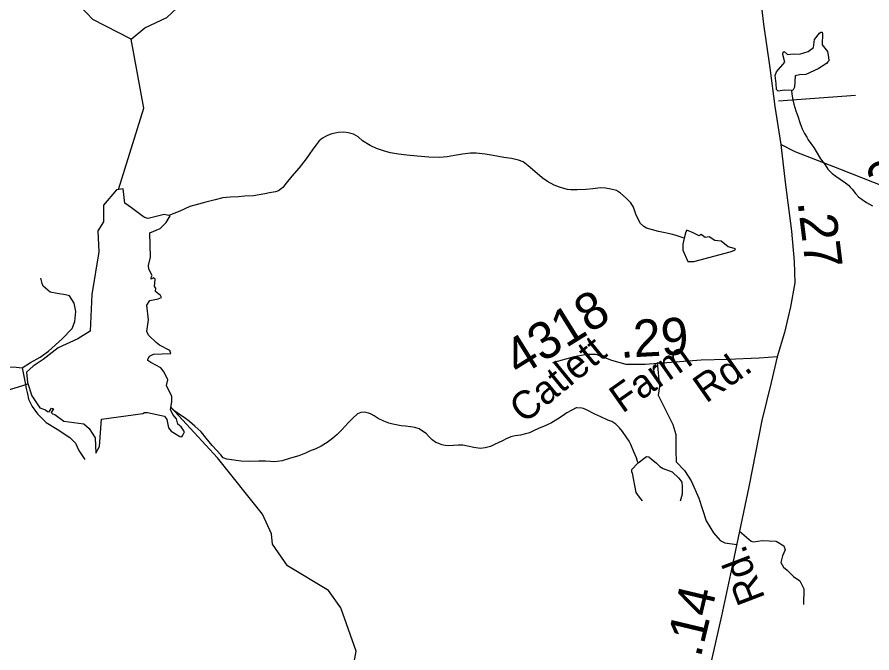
# Model space of a CAD drawing. Extents: x 2001466 to 31450019, y -30647475 to 847247.
# Drawn here: x 2159166 to 2164923, y 778978 to 783261 of the extents above; entities that cross this region are included whole.
import ezdxf

# ---------------------------------------------------------------- set-up
doc = ezdxf.new("R2010")
doc.units = 0
for name, color, linetype in [('Exist Hydrographic Creek Single Shore', 7, 'Continuous'), ('Exist Hydrographic Misc Water Feature', 7, 'Continuous'), ('Exist Hydrographic Pond Under 1500 Sq Ft', 7, 'Continuous'), ('Exist Road Non-System Type 51', 7, 'Continuous'), ('Exist Road Secondary Mileage Hundredths English Label', 7, 'Continuous'), ('Exist Road Secondary Type 51 Attributed', 7, 'Continuous'), ('Exist Road Secondary Type 51 Label', 7, 'Continuous'), ('Exist Road Secondary Type 51 Number Label', 7, 'Continuous')]:
    doc.layers.add(name, color=color, linetype=linetype)

msp = doc.modelspace()

# ---------------------------------------------------------------- linework, layer by layer
at = {"layer": 'Exist Hydrographic Creek Single Shore'}
for points in [[(2159934.2, 783111.8), (2159675.2, 783245.1), (2159591.3, 783335.4), (2159564.3, 783677.1), (2159497.2, 783826.2), (2159545.2, 784195.9), (2159543.3, 784428.8), (2159483.3, 784702.3), (2159457.2, 784952.2), (2159562.2, 785570.1), (2159692.2, 786062.8), (2159666.2, 786201.1), (2159591.3, 786284.7), (2159548.3, 786518.4), (2159498.2, 786627.7), (2159347.3, 786758.8), (2159419.3, 787226.4), (2159543.3, 787335.5), (2159609.2, 787462), (2159684.2, 787519.5), (2159784.3, 787537.1)], [(2159849.3, 782099.5), (2160020.3, 782647.6), (2159934.2, 783111.8)], [(2157629.3, 780016.8), (2157644.3, 780009.6), (2157785.2, 780052.6), (2157860.3, 780119.9), (2158251.3, 780203.7), (2158798.2, 780625.5), (2158914.2, 780692), (2159203.8, 780779.7)], [(2159203.8, 780779.7), (2159239.1, 780790.4)], [(2162195.3, 776678.1), (2161700.3, 777183.6), (2161565.1, 777498.1), (2161429.2, 777940.4), (2161419.2, 778298.2), (2161385.3, 778364.5), (2161376.3, 778581.3), (2161449.3, 778989.8), (2161347.2, 779280.6), (2161263.3, 779397.2), (2160987.3, 779563.5), (2160886.2, 779710), (2160878.2, 779779), (2160818.1, 779911.5), (2160516.3, 780291.7), (2160201, 780633.1)]]:
    msp.add_lwpolyline(points, dxfattribs=at)
at = {"layer": 'Exist Hydrographic Misc Water Feature'}
for points in [[(2159934.2, 783111.8), (2160025.2, 783188.7), (2160175.3, 783257.8), (2160240.9, 783320.9)], [(2164380.8, 782765.9), (2164384.2, 782742.2), (2164390.8, 782702.3), (2164396.7, 782674.2), (2164411.1, 782628.2), (2164423.8, 782594.2), (2164439.8, 782544.4), (2164453.7, 782508.6), (2164470.1, 782476.5), (2164484.5, 782450.8), (2164494.3, 782433.1), (2164512.8, 782408.8), (2164532.7, 782383), (2164548.9, 782355.1), (2164577.2, 782305.3), (2164607.5, 782265.4), (2164627.2, 782235.7), (2164655.7, 782207.8), (2164679.5, 782190), (2164709.6, 782170), (2164745.7, 782144.3), (2164766, 782128.3), (2164777.9, 782114.7), (2164790, 782100.7), (2164811.9, 782072.6), (2164832.2, 782050.9), (2164858.7, 782031.1), (2164886.4, 782011.1), (2164927, 781989.5)], [(2163658.6, 781771.1), (2163638.2, 781778.3), (2163604.4, 781789.9), (2163570.4, 781799.6), (2163530, 781807.7), (2163486.1, 781817.1), (2163446.1, 781826.9), (2163406.1, 781839), (2163388.1, 781850.7), (2163365.7, 781870.7), (2163352, 781894.7), (2163333.5, 781932.3), (2163317.3, 781980.2), (2163298.9, 782010.2), (2163268.5, 782041.9), (2163230.8, 782075.7), (2163202.5, 782091.7), (2163164.6, 782101.5), (2163128.7, 782107.3), (2163094.2, 782110.9), (2163042.8, 782104.5), (2162996.6, 782100.5), (2162938.8, 782097.9), (2162894.5, 782097.7), (2162872.8, 782099.8), (2162848.6, 782105.5), (2162818.4, 782115.3), (2162782.5, 782129.2), (2162738.5, 782153), (2162702.4, 782178.7), (2162654, 782220.5), (2162608, 782258.3), (2162574, 782285.7), (2162542, 782297.9), (2162495.5, 782307.3), (2162443.4, 782315.2), (2162371.6, 782328.9), (2162317.7, 782336.6), (2162257.4, 782344.2), (2162219.5, 782343.8), (2162165.7, 782337.7), (2162111.2, 782327.3), (2162061.8, 782319), (2162014, 782314.9), (2161940, 782316.3), (2161860, 782323.9), (2161791.5, 782331.5), (2161735.5, 782337.1), (2161681.4, 782346.9), (2161641.4, 782356.6), (2161587.5, 782376.5), (2161543.6, 782396.1), (2161493.2, 782427.7), (2161463, 782453.7), (2161431, 782471.6), (2161395, 782481.1), (2161367.1, 782484.9), (2161327.3, 782482.8), (2161307, 782478.6), (2161286.7, 782474.8), (2161272.9, 782470.8), (2161247.1, 782458.4), (2161223.5, 782444.1), (2161201.2, 782428.1), (2161179.7, 782400.1), (2161157.5, 782370.1), (2161133.5, 782335.6), (2161112, 782305.6), (2161066.3, 782245.6), (2161016.8, 782189), (2160977.1, 782143.1), (2160955.3, 782112.7), (2160945.3, 782102.8), (2160927, 782090.6), (2160907.3, 782082.6), (2160865.5, 782076.3), (2160833.5, 782070.2), (2160757.4, 782057.8), (2160699.2, 782055.3), (2160657.4, 782051.1), (2160599.8, 782046.8), (2160551.8, 782042.7), (2160499.7, 782030.3), (2160438, 782014.1), (2160387.7, 782001.7), (2160329.9, 781985.4), (2160262.5, 781953), (2160187.5, 781923.7)], [(2160009.1, 781921.1), (2159936.6, 781975.4), (2159891.3, 782006.7), (2159880.8, 782104.4), (2159835.5, 782097.4), (2159748.4, 781992.8), (2159748.4, 781881.2), (2159710, 781821.9), (2159717, 781679), (2159668.2, 781393), (2159657.8, 781145.4), (2159574.1, 781093.1), (2159441.7, 781033.8), (2159340.7, 780953.6), (2159274.4, 780908.3), (2159229.1, 780870), (2159236.1, 780800.2), (2159264, 780709.5), (2159319.7, 780629.3), (2159356.7, 780614.8), (2159371.3, 780604.7), (2159381.3, 780601.1), (2159398.6, 780627.5), (2159412.1, 780621.8), (2159395.9, 780597.4), (2159404.3, 780589.2), (2159420.8, 780584), (2159480, 780538.7), (2159616, 780521.2), (2159650.8, 780489.9), (2159692.6, 780427.1), (2159696.1, 780322.5), (2159720.5, 780367.8), (2159734.4, 780552.6), (2160012.4, 780590.2)], [(2160012.4, 780590.2), (2160024.9, 780596.8), (2160044.8, 780597.7), (2160158.7, 780573.6), (2160174.5, 780550.3), (2160185.3, 780493.7), (2160203.6, 780470.4), (2160225.2, 780457.1), (2160261, 780436.3), (2160275.1, 780433.8), (2160281.7, 780444.6), (2160293.4, 780467.1), (2160271.8, 780500.4), (2160247.6, 780518.7), (2160238.5, 780555.3), (2160214.4, 780583.5), (2160198.6, 780618.5), (2160206.9, 780668.4), (2160208.6, 780704.1), (2160172, 780779.8), (2160181.1, 780817.6), (2160156.2, 780869.2), (2160132.9, 780898.3), (2160066.4, 780934.9), (2160047.3, 780947.4), (2160045.7, 780956.2), (2160057.3, 780975.6), (2160085.6, 780989.8), (2160200.3, 780995.6), (2160194.4, 781013.9), (2160125.5, 781050.5), (2160103, 781068.6), (2160049.8, 781118.5), (2160039, 781142.5), (2160049.8, 781221.7), (2160039.8, 781319.2), (2160059.8, 781352.5), (2160116.3, 781362.4), (2160138.8, 781371.6), (2160132.1, 781385.7), (2160098.9, 781412.3), (2160101.3, 781434), (2160092.2, 781445.3), (2160094.7, 781496.3), (2160083.9, 781503.8), (2160069.8, 781494.7), (2160068.1, 781506.3), (2160076.4, 781519.6), (2160054, 781562.9), (2160051.5, 781587.8), (2160063.9, 781642.7), (2160059, 781807.9), (2160130.4, 781837.4), (2160170.3, 781876.5), (2160197.8, 781921.4), (2160155.4, 781931), (2160049, 781904.4), (2160023.2, 781911.4), (2160009.1, 781921.1)], [(2163658.6, 781771.1), (2163650.4, 781730.8), (2163649.1, 781691), (2163683.4, 781613.4), (2163724.6, 781615.4), (2163969.6, 781680), (2163999.8, 781690.3), (2164005.3, 781700.6), (2163954.5, 781712.3), (2163908.5, 781750.7), (2163885.9, 781752.8), (2163864.6, 781755.5), (2163827.5, 781781), (2163800.1, 781776.2), (2163774, 781795.4), (2163760.3, 781787.8), (2163719.8, 781806.4), (2163677.2, 781824.9), (2163669.7, 781815.3), (2163658.6, 781771.1)], [(2160553.4, 780291.1), (2160537.6, 780313), (2160511.2, 780340.9), (2160479.4, 780374.6), (2160438.8, 780424.5), (2160405, 780466.1), (2160362.7, 780505.8), (2160326.4, 780537.6), (2160292, 780563.5), (2160260, 780583.4), (2160227.8, 780607.3), (2160200.6, 780630.2)], [(2162931.2, 780628.5), (2162902.9, 780612.1), (2162869.3, 780594), (2162837.3, 780572.1), (2162805.3, 780551.8), (2162765.5, 780527.4), (2162727.8, 780509.1), (2162677.8, 780489.1), (2162643.9, 780472.7), (2162616, 780460.7), (2162590, 780452.5), (2162556, 780444.3), (2162520.3, 780440.3), (2162492.2, 780434), (2162460, 780419.8), (2162434.8, 780405.8), (2162410.6, 780395.7), (2162380.6, 780381.5), (2162354.2, 780369.3), (2162318.7, 780359.2), (2162284.7, 780355), (2162242.8, 780360.6), (2162199, 780370.5), (2162168.4, 780376.3), (2162138.5, 780377.9), (2162104.6, 780375.8), (2162070.8, 780373.6), (2162048.5, 780375.4), (2162026.7, 780379.5), (2162006.2, 780387.4), (2161986.3, 780395.3), (2161962.5, 780413.1), (2161942, 780432.8), (2161920.1, 780454.8), (2161896.5, 780470.6), (2161874, 780486.5), (2161844.2, 780496.3), (2161815.9, 780500.2), (2161781.9, 780504.2), (2161751.7, 780507.8), (2161720, 780513.5), (2161696, 780519.5), (2161669.7, 780525.5), (2161635.5, 780539.2), (2161597.5, 780556.7), (2161569.7, 780574.7), (2161549.6, 780586.7), (2161535.6, 780592.5), (2161503.2, 780600.2), (2161481.3, 780598.3), (2161457.5, 780588.1), (2161427.8, 780560.1), (2161400.1, 780531.8), (2161376.3, 780505.8), (2161350.3, 780477.3), (2161320.5, 780449.3), (2161290.6, 780423.1), (2161254.5, 780395.2), (2161214.7, 780370.8), (2161177, 780352.6), (2161135.2, 780336.2), (2161109.3, 780324.3), (2161063.2, 780305.7), (2161007.6, 780289.8), (2160951.4, 780271.5), (2160917.4, 780266.9), (2160889.9, 780265), (2160871.5, 780267), (2160839.5, 780268.5), (2160793.5, 780268.6), (2160732, 780268.2), (2160675.6, 780269.8), (2160642, 780273.7), (2160609.8, 780277.3), (2160579.3, 780283.2), (2160553.4, 780291.1)], [(2163349.7, 780259), (2163344.8, 780267), (2163337, 780290.8), (2163320.6, 780332.7), (2163300.5, 780380.8), (2163287.8, 780404.5), (2163267.7, 780434.4), (2163243.7, 780468.4), (2163223.8, 780494.2), (2163197.6, 780518), (2163171.5, 780535.7), (2163145.3, 780545.8), (2163097.3, 780567.3), (2163057.3, 780587.1), (2163005, 780612.8), (2162981, 780624.6), (2162969.1, 780626.8), (2162934.8, 780628.3), (2162931.2, 780628.5)], [(2163349.7, 780259), (2163404.1, 780299.9), (2163421.5, 780298.2), (2163437.3, 780284.1), (2163473.1, 780256.6), (2163494.7, 780234.2), (2163517.1, 780220), (2163577, 780197.6), (2163623.5, 780154.3), (2163643.5, 780126.9), (2163645.1, 780096.9), (2163644.3, 780047), (2163632.7, 779999.6)], [(2163349.7, 780259), (2163304.3, 780211.7), (2163303.5, 780200.9), (2163309.3, 780189.3), (2163332.6, 780058.7), (2163356.7, 780027.9), (2163376.6, 780001.3)]]:
    msp.add_lwpolyline(points, dxfattribs=at)
at = {"layer": 'Exist Hydrographic Pond Under 1500 Sq Ft'}
msp.add_lwpolyline([(2164395.1, 783014), (2164436.5, 783010.9), (2164494.9, 783027.9), (2164529.6, 783055.3), (2164537.3, 783110.6), (2164571.2, 783153.1), (2164578.6, 783158.4), (2164587.1, 783159.4), (2164591.4, 783150.9), (2164589.3, 783073.4), (2164624.5, 783029.1), (2164630.2, 782990.4), (2164632.1, 782967.2), (2164625.6, 782959.2), (2164617.9, 782948.8), (2164561.7, 782913.3), (2164477.9, 782875.1), (2164435.3, 782872.9), (2164407, 782864.8), (2164402.6, 782788), (2164389.9, 782766.8), (2164335.5, 782768.1), (2164292.3, 782762.6), (2164281.7, 782773.2), (2164278.5, 782812.4), (2164272.2, 782866.6), (2164280.5, 782891.7), (2164336.8, 782957.8), (2164323.1, 783007.7), (2164325.2, 783024.7), (2164331.5, 783030), (2164353.8, 783009.8), (2164395.1, 783014)], dxfattribs=at)
at = {"layer": 'Exist Road Non-System Type 51'}
msp.add_line((2164812.5, 782732.9), (2164293.7, 782693.5), dxfattribs=at)
for points in [[(2159200, 780898.7), (2159257.1, 780934), (2159320.9, 780970.9), (2159376.3, 781009.6), (2159468.6, 781093.6), (2159535.7, 781162.4), (2159554.2, 781211.1), (2159560.9, 781276.6), (2159550.8, 781333.7), (2159518.9, 781384.1), (2159492.1, 781390.9), (2159435, 781399.3), (2159388, 781407.7), (2159342.1, 781448.6), (2159334.3, 781466.4), (2159325.9, 781501.7)], [(2163476, 780933.6), (2163492.1, 780773.2), (2163484.1, 780714.4), (2163582.9, 780516.6), (2163601.6, 780449.8), (2163601.6, 780340.2), (2163604.3, 780265.4), (2163660.4, 780206.6), (2163705.8, 780137.1), (2163756.6, 780019.5), (2163807.3, 779867.1), (2163855.4, 779786.9), (2163900.8, 779736.1), (2163932.9, 779720.1), (2164012.9, 779707.3)], [(2157623, 780359.6), (2157789.5, 780356.2), (2157997.6, 780430.1), (2158131.9, 780463.7), (2158224.2, 780534.2), (2158276.2, 780584.6), (2158342.3, 780626.6), (2158555.5, 780700.5), (2158755.2, 780804.7), (2158866, 780850), (2158983.5, 780890.3), (2159054, 780905.4), (2159159.8, 780902.1), (2159200, 780898.7)], [(2159200, 780898.7), (2159220.2, 780796.3), (2159226.9, 780759.3)], [(2159226.9, 780759.3), (2159235.3, 780722.4), (2159243, 780687), (2159267.2, 780636.7), (2159302.4, 780588), (2159361.2, 780530.9), (2159435, 780485.5), (2159520.6, 780428.4), (2159559.2, 780389.8), (2159582.7, 780341.1), (2159621.3, 780280.6)], [(2164030.4, 779797.6), (2164109.5, 779730.6), (2164125.4, 779726.2), (2164184, 779736.1), (2164277.5, 779730.8), (2164330.9, 779698.7), (2164338.9, 779672), (2164320.2, 779631.9), (2164309.6, 779586.4), (2164328.3, 779554.4), (2164352.3, 779535.7), (2164395, 779492.9), (2164437.8, 779463.5), (2164464.5, 779410), (2164461.8, 779303.1)]]:
    msp.add_lwpolyline(points, dxfattribs=at)
at = {"layer": 'Exist Road Secondary Type 51 Attributed'}
for points in [[(2163686.4, 786619.3), (2163781.1, 786437.1), (2163833.4, 786288.4), (2163862.7, 786123), (2163926.6, 785653.9), (2163953.8, 785285.3), (2164051.1, 784468.5), (2164125.4, 783787.9), (2164192.3, 783214), (2164235.2, 782918.8), (2164268.7, 782659.1), (2164309.5, 782403.6)], [(2164309.5, 782403.6), (2164339.9, 782148.1), (2164381.7, 781819.3), (2164400.6, 781614), (2164403.7, 781471.6), (2164374.4, 781308.3), (2164334.6, 781136.5), (2164284.4, 780973.2)], [(2169124.5, 780265.3), (2169019.3, 780366.9), (2168762.4, 780554.3), (2168591.9, 780686.3), (2168352.8, 780822.4), (2168065, 780972.1), (2167610.4, 781184.7), (2167493.2, 781233.9), (2167387.5, 781266.4), (2167258.8, 781295.7), (2167043.7, 781333.4), (2166917.1, 781364.8), (2166773.8, 781414), (2166391.3, 781551.2), (2166256.3, 781602.5), (2166139.1, 781670.6), (2165956.5, 781786.8), (2165853, 781838.1), (2165755.6, 781864.3), (2165522.3, 781937.6), (2165089.6, 782085.2), (2164706.6, 782236), (2164405.3, 782353.3), (2164309.5, 782403.6)], [(2164284.4, 780973.2), (2164163.6, 780963.8), (2163951.1, 780954.3), (2163772.2, 780950.2), (2163395, 780920.8), (2163268.4, 780920.8), (2163171.1, 780947), (2163066.4, 780986.8), (2163004.7, 780987.9), (2162917.8, 780971.1), (2162772.8, 780931)], [(2164284.4, 780973.2), (2164245.2, 780799.4), (2164181.4, 780543.9), (2164093.5, 780095.7), (2163977.3, 779542.8), (2163910.3, 779226.6), (2163796.3, 778721.9), (2163716.8, 778382.6), (2163588.1, 777771.1), (2163479.2, 777272.7), (2163384, 776814), (2163287.7, 776303), (2163205.1, 775972.1), (2163136, 775676.8), (2163052.3, 775354.3), (2163018.8, 775205.6)]]:
    msp.add_lwpolyline(points, dxfattribs=at)

# ---------------------------------------------------------------- texts
at = {"layer": 'Exist Road Secondary Mileage Hundredths English Label'}
for s, rotation, p in [('.27', 277.12138, (2164422.1, 782015.1)), ('.29', 3.17617, (2163229.3, 780964.6)), ('1.14', 76.54778, (2163726, 778759.6))]:
    msp.add_text(s, height=250, rotation=rotation, dxfattribs=at).set_placement(p)
at = {"layer": 'Exist Road Secondary Type 51 Label'}
for s, rotation, p in [('Catlett', 39.27417, (2162581.1, 780517.3)), ('Farm', 35.0942, (2163242.6, 780587.5)), ('Rd.', 35.0942, (2163806.2, 780655.7)), ('Rd.', 110.9845, (2164206.3, 779347.7))]:
    msp.add_text(s, height=190, rotation=rotation, dxfattribs=at).set_placement(p)
at = {"layer": 'Exist Road Secondary Type 51 Number Label'}
for s, p in [('2308', (2164989.9, 782011.5)), ('4318', (2162546.9, 780832.5))]:
    msp.add_text(s, height=250, rotation=31.91803, dxfattribs=at).set_placement(p)

doc.saveas('drawing.dxf')
